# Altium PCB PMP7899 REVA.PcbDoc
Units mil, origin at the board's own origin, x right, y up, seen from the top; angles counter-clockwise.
Board outline 4000 x 1400 mil, 4 copper layers (Top Layer, MidLayer1, MidLayer2, Bottom Layer), stack 62.6 mil thick; 69 components, 27 nets, 146 pads, 45 vias.
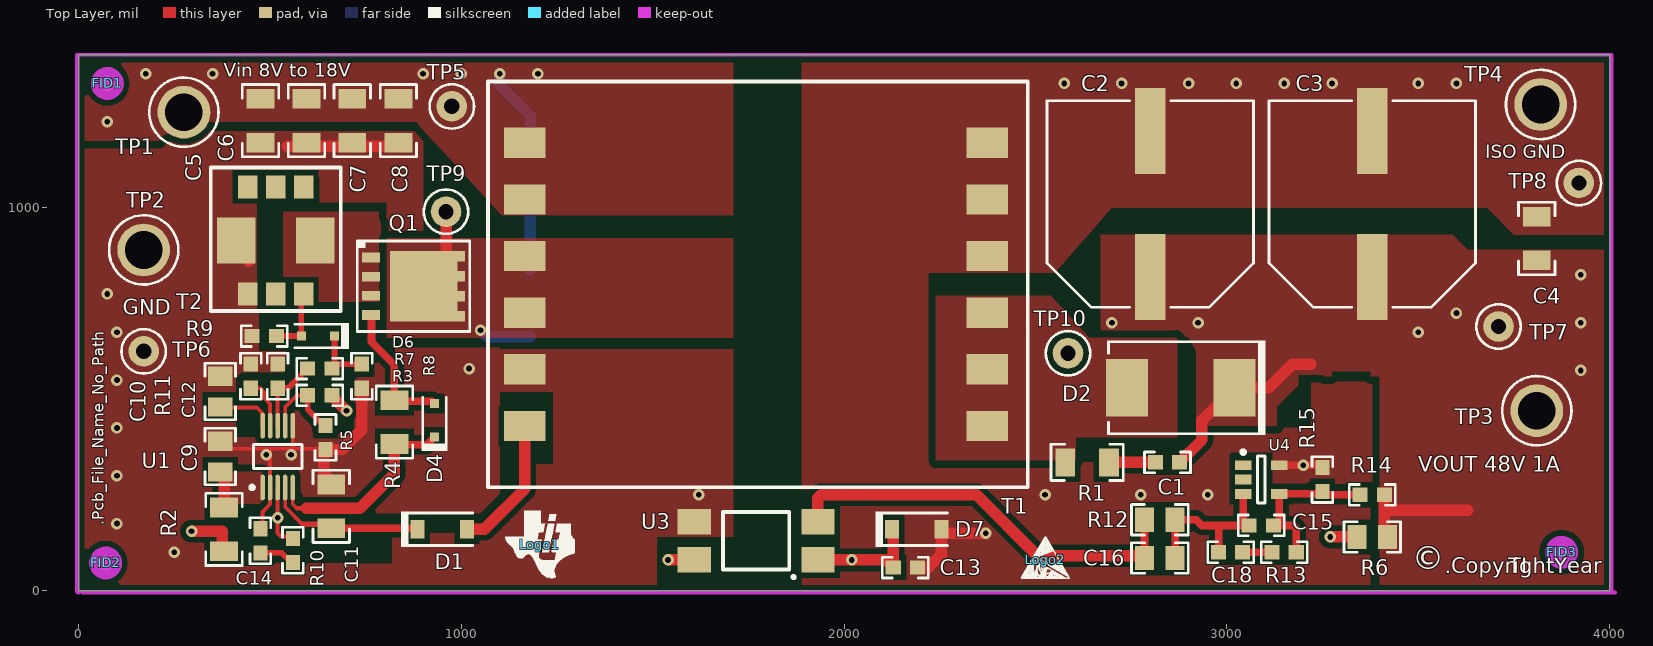
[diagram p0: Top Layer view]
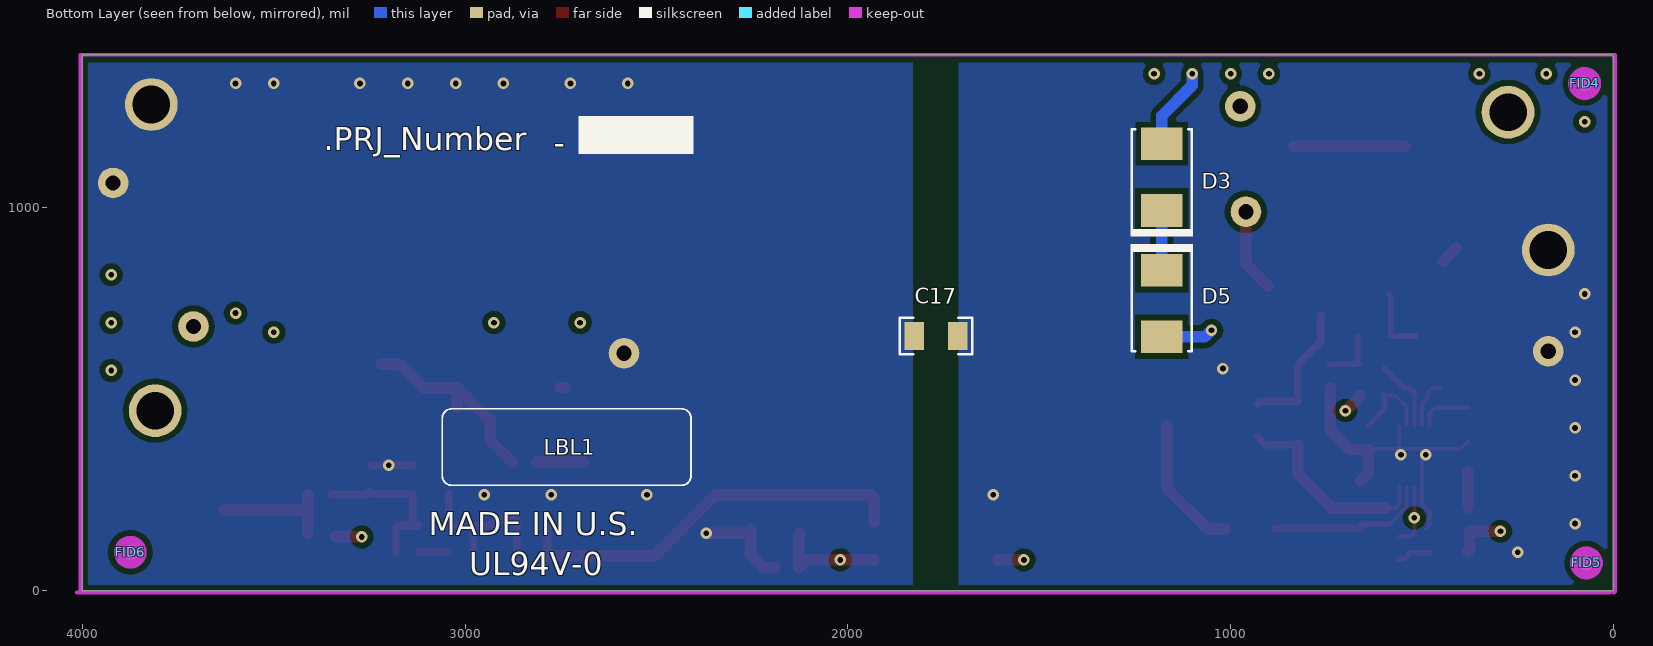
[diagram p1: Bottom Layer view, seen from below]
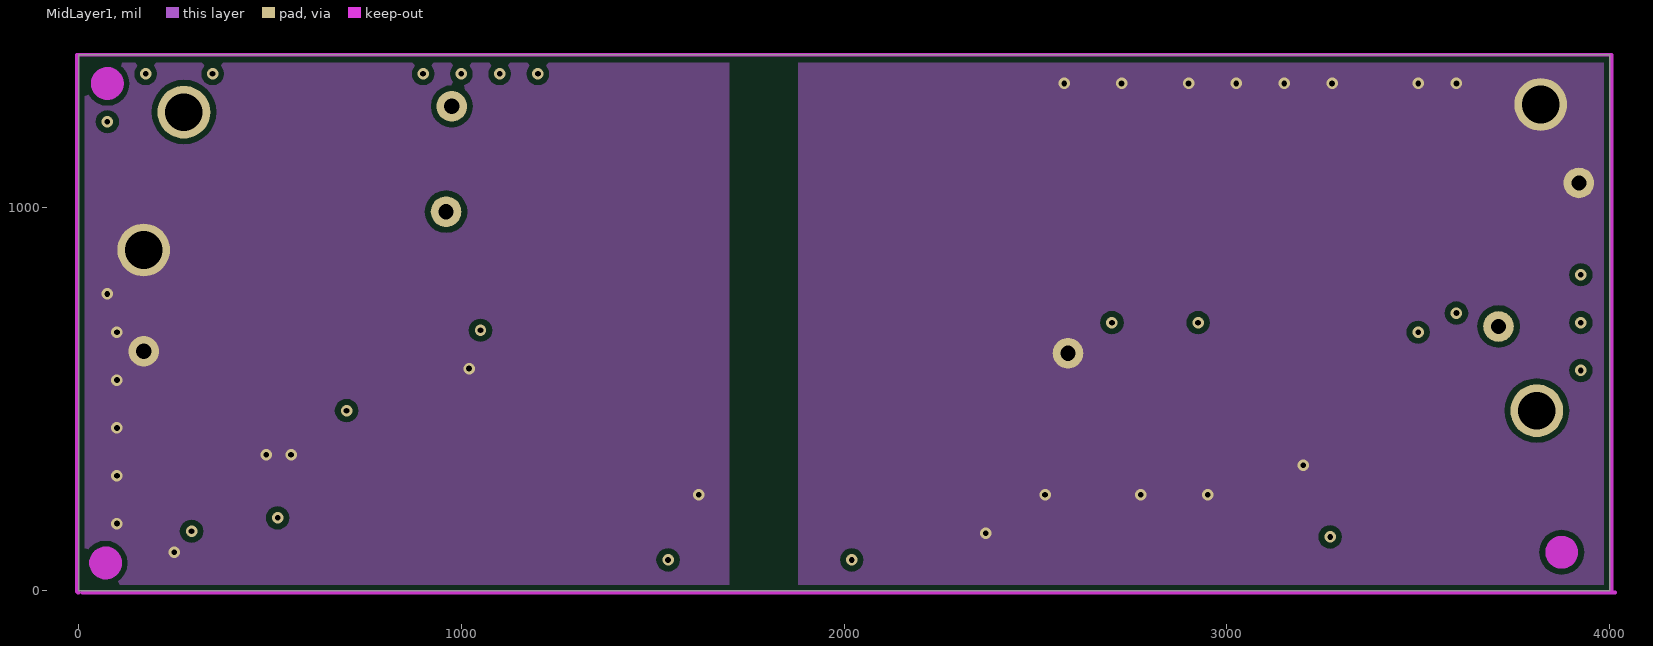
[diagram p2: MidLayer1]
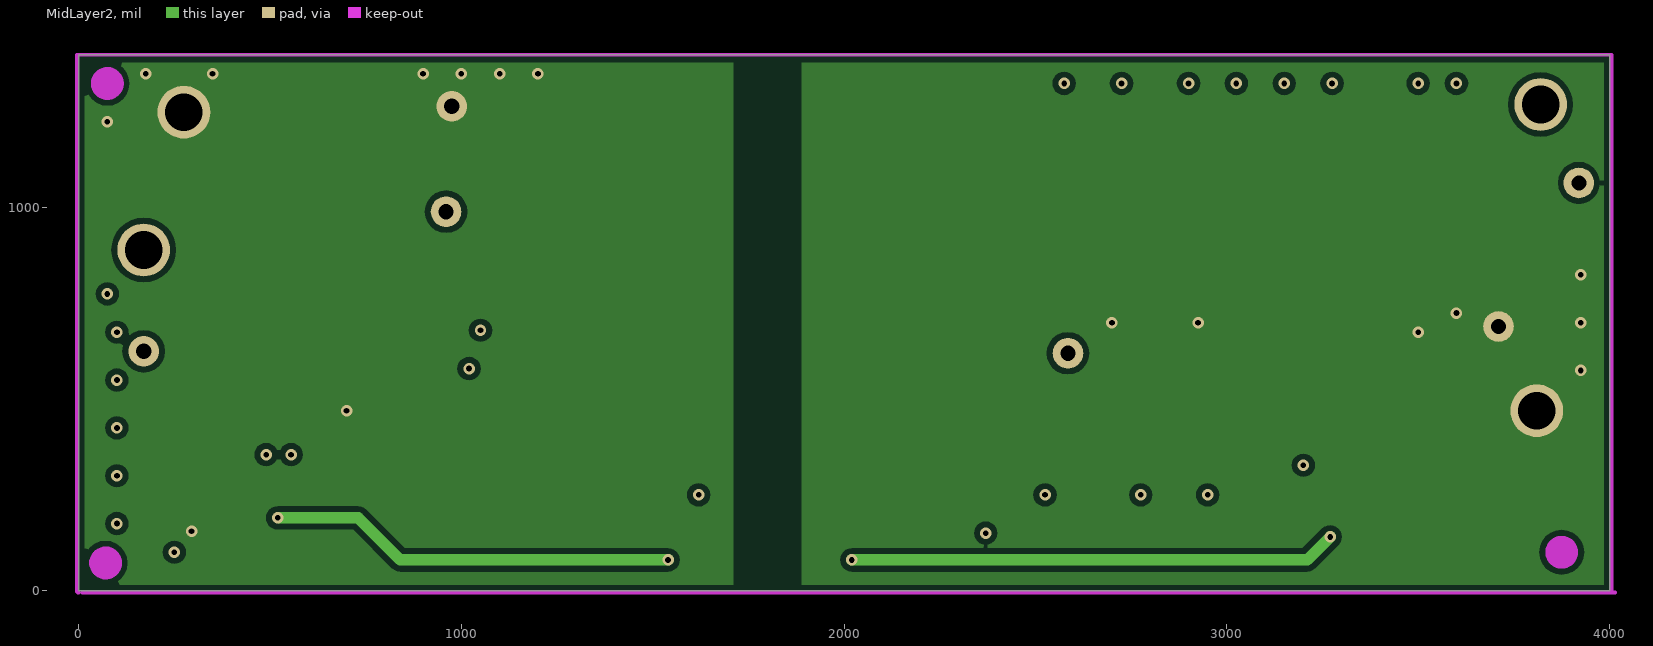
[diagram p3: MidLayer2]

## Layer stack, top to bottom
Top Layer: signal copper 1.4
Dielectric: prepreg 19, FR-4, Dk 4.8
MidLayer1: signal copper 1.4
Dielectric: core 19, FR-4, Dk 4.8
MidLayer2: signal copper 1.4
Dielectric: prepreg 19, FR-4, Dk 4.8
Bottom Layer: signal copper 1.4

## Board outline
0,0 0,1400 4000,1400 4000,0

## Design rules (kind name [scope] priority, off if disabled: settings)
AcuteAngle [All] p1: minimum=4.50000000000000E+0001 checktracksonly=FALSE
AssemblyTestPointUsage [All] p1: valid=2
Clearance "Clearance_Polygon to Polygon" [IsRegion vs IsRegion] p1: gap=20
Clearance Clearance_Polygon [IsRegion] p2: gap=15
Clearance Clearance_BoardEdge_MountingHoles [OnCopper and InComponentClass('Mounting Holes') vs IsKeepOut] p3: gap=40
Clearance Clearance_BoardEdge_Poly [OnCopper and InPoly vs IsKeepOut] p4: gap=25
Clearance Clearance_BoardEdge [OnCopper and Not InComponentClass('Logo') and not InComponentClass('FiducialMark') and not InRegion(1000,500,4000,800) vs IsKeepOut] p5: gap=75
Clearance [All] p6: gap=10
ComponentClearance ComponentClearance_Logo [InComponentClass(Logo)] p1: gap=50 collisioncheckmode=3 verticalgap=10 showdistances=FALSE
ComponentClearance ComponentClearance_ScrewToNut [(HasFootprint('NY PMS 440 0025 PH')) vs (HasFootprint('Keystone_1902C'))] p2: gap=5 collisioncheckmode=3 verticalgap=10 showdistances=FALSE
ComponentClearance ComponentClearance_MountingHoles [InComponentClass('Mounting Holes')] p3: gap=250 collisioncheckmode=3 verticalgap=100000 showdistances=FALSE
ComponentClearance ComponentClearance_SmallPassives [HasFootprint('0201*') or HasFootprint('0402*') or HasFootprint('0508') or HasFootprint('0603*') or HasFootprint('0612') or HasFootprint('0805*') or HasFootprint('0815*') or HasFootprint('0830*') or HasFootprint('1206*') or HasFootprint('1210*') or HasFootprint('1808*') or HasFootprint('1812*') or HasFootprint('1825*') or HasFootprint('2010*') or HasFootprint('2220*') or HasFootprint('2225*') or HasFootprint('2512*') or HasFootprint('2728*') or HasFootprint('3518*') vs HasFootprint('0201*') or HasFootprint('0402*') or HasFootprint('0508') or HasFootprint('0603*') or HasFootprint('0612') or HasFootprint('0805*') or HasFootprint('0815*') or HasFootprint('0830*') or HasFootprint('1206*') or HasFootprint('1210*') or HasFootprint('1808*') or HasFootprint('1812*') or HasFootprint('1825*') or HasFootprint('2010*') or HasFootprint('2220*') or HasFootprint('2225*') or HasFootprint('2512*') or HasFootprint('2728*') or HasFootprint('3518*')] p4: gap=20 collisioncheckmode=3 verticalgap=10 showdistances=FALSE
ComponentClearance ComponentClearance_THtoSMT [IsThruComponent vs IsSMTComponent] p5: gap=100 collisioncheckmode=3 verticalgap=100000 showdistances=FALSE
ComponentClearance ComponentClearance_THtoTH [IsThruComponent vs IsThruComponent] p6: gap=118.11 collisioncheckmode=3 verticalgap=100000 showdistances=FALSE
ComponentClearance [All] p7: gap=40 collisioncheckmode=3 verticalgap=10 showdistances=FALSE
DiffPairsRouting [All] p1: maxlimit=100 minlimit=10 mostfreqgap=10 maxuncoupledlength=1000
FabricationTestPointUsage TestPointUsage [All] p1: valid=2 allowmultiple=FALSE
FabricationTestpoint Testpoint [All] p1: side=3 testpointundercomponent=TRUE minsize=40 maxsize=100 preferedsize=60 minholesize=0 maxholesize=40 preferedholesize=32 testpointgrid=1 allowsidetop=TRUE allowsidebottom=TRUE usegrid=TRUE gridtolerance=0.01
FanoutControl Fanout_LCC [IsLCC] p1: bgadir=Out bgaviamode=Centered fanoutstyle=Auto fanoutdirection=Alternating viagrid=1 // Fanout_LCC (Default Rule)
FanoutControl Fanout_BGA [IsBGA] p2: bgadir=Out bgaviamode=Centered fanoutstyle=Auto fanoutdirection=Alternating viagrid=1 // Fanout_BGA (Default Rule)
FanoutControl Fanout_Default [All] p4: bgadir=Out bgaviamode=Centered fanoutstyle=Auto fanoutdirection=Alternating viagrid=1 // Fanout_Default (Default Rule)
FanoutControl Fanout_Small [(CompPinCount < 5)] p5: bgadir=Out bgaviamode=Centered fanoutstyle=Auto fanoutdirection=OutThenIn viagrid=1 // Fanout_Small (Default Rule)
HoleSize [All] p1: absolutevalues=TRUE maxlimit=251 minlimit=8 maxpercent=80.000 minpercent=20.000
MinimumAnnularRing [All] p1: minimumring=6
MinimumSolderMaskSliver MinimumSolderMaskSliver_Logo [InComponentClass('Logo') vs InComponentClass('Logo')] p1: minsoldermaskwidth=0.7
MinimumSolderMaskSliver [All] p2: minsoldermaskwidth=4
PlaneConnect [All] p1: planeconnectstyle=Relief reliefexpansion=10 reliefentries=4 reliefconductorwidth=10 reliefairgap=10
PolygonConnect [All] p1: connectstyle=Direct reliefconductorwidth=10 reliefentries=4 polygonreliefangle="90 Angle" airgapwidth=10
RoomDefinition "PMP7899 schematic Rev3" [InComponentClass('PMP7899 schematic Rev3')] p1 off: confinementstyle=ConfineIn formatcopy=TRUE lockcomponents=FALSE outline -692,-1534 1308,-1534 1308,-534 -692,-534
RoutingVias [All] p1: holewidth=16 width=34 viastyle="Through Hole" minholewidth=8 minwidth=26 maxholewidth=40 maxwidth=65
SMDToCorner [All] p1: distance=30000
SilkToSilkClearance [All] p1: silktosilkclearance=5
SilkscreenOverComponentPads [All] p1: minsilkscreentomaskgap=5
SolderMaskExpansion [All] p1: expansion=3
Width [All] p1: maxlimit=100 minlimit=10 preferedwidth=10 checkconnectedcopper=TRUE
14 further rules are at their usual default settings.

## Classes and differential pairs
component class "PMP7899 schematic Rev3": C1 C2 C3 C4 C5 C6 C7 C8 C9 C10 C11 C12 C13 C14 C15 C16 C17 C18 D1 D2 D3 D4 D5 D6 D7 Q1 R1 R2 R3 R4 R5 R6 R7 R8 R9 R10 R11 R12 R13 R14 R15 T1 T2 TP1 TP2 TP3 TP4 TP5 TP6 TP7 TP8 TP9 TP10 U1 U3 U4
component class Logo: Logo1
component class Hardware_ANSI-B: FID1 FID2 FID3 FID4 FID5 FID6 LBL1 Logo1 Logo2 ZZ1 ZZ2 ZZ3 ZZ4
component class FiducialMark: FID1 FID2 FID3 FID4 FID5 FID6
component class AssemblyNote: ZZ1 ZZ2 ZZ3 ZZ4
component class Label: LBL1

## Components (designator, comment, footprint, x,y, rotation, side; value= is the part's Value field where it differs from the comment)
C1 "C1608C0G2A101J" 0603 2845,335 r180 top
C2 "Panasonic, EEV-FK1J151Q" SM_RADIAL_H13 2800,1010 r90 top
C3 "EEV-FK1J151Q" SM_RADIAL_H13 3380,1010 r90 top
C4 "GRM31MR71H105KA88L" 1206 3810,920 r90 top
C5 "GRM31CR71E106KA12L" 1206 475,1227.52 r270 top
C6 "GRM31CR71E106KA12L" 1206 595,1227.52 r270 top
C7 "GRM31CR71E106KA12L" 1206 715,1227.52 r270 top
C8 "GRM31CR71E106KA12L" 1206 835.32,1227.52 r270 top
C9 "C2012X5R1E105K" 0805_HV 370,350 r90 top
C10 "C2012C0G1E103J" 0805_HV 370,520 r90 top
C11 "GRM31CR61E106KA12L" 1206 660,220 r90 top
C12 "C1608C0G1H101J" 0603 520,560 r90 top
C13 "GRM188R61C105KA93D" 0603 2160,60 r0 top
C14 "C0603C104K3RACTU" 0603 475,130 r90 top
C15 "C1608C0G2A101J" 0603 3090,170 r0 top
C16 "C2012Y5V1H105Z" 0805_HV 2825,85 r180 top
C17 "C1206C102KFRACTU" 1206 1770,665 r180 bottom
C18 "C0603C104J3RACTU" 0603 3010,100 r180 top
D1 "1N4148W-7-F" SOD-123 950,160 r0 top
D2 "ES3J" SMC 2880,530 r180 top
D3 "DNP, On Semi, 1SMB5939BT3G" SMB 1180,1080 r90 bottom
D4 "BAT54HT1G" sod-323 930,445 r90 top
D5 "DNP, Diodes Inc, MBRS1100T3G" SMB 1180,750 r270 bottom
D6 "BAT54HT1G" sod-323 625,665 r180 top
D7 "Vishay, MMSZ4699-V" SOD-123 2190,160 r0 top
FID1 "Fiducial" Fiducial10-20 75,1325 r0 top
FID2 "Fiducial" Fiducial10-20 70.46,72.11 r0 top
FID3 "Fiducial" Fiducial10-20 3875,100 r0 top
FID4 "Fiducial" Fiducial10-20 75,1325 r180 bottom
FID5 "Fiducial" Fiducial10-20 70.46,72.11 r180 bottom
FID6 "Fiducial" Fiducial10-20 3875,100 r180 bottom
LBL1 "Size: 0.65\" x 0.20 \"" Label_650x200 2735,375 r180 bottom
Logo1 "Texas Instruments" TI_Symbol_Overlay_Small 1205,120 r0 top
Logo2 "ESD Susceptible" ESD_Overlay_Small 2525,80 r0 top
Q1 "Infineon, BSC067N06LS3 G" PG-TDSON-8 875,795 r0 top
R1 "CRCW1206100RFKEA" 1206 2635,335 r180 top
R2 "CRCW12063R32FKEA" 1206 380,160 r270 top
R3 "CRCW060346K4FKEA" 0603 630,510 r0 top
R4 "CRCW12060000Z0EA" 1206 825,440 r270 top
R5 "CRCW060310K0FKEA" 0603 645,400 r90 top
R6 "CRCW080510K0FKEA" 0805_HV 3380,140 r0 top
R7 "CRCW06031K00FKEA" 0603 630,580 r0 top
R8 "CRCW06033R01FKEA" 0603 740,560 r90 top
R9 "CRCW060310K0FKEA" 0603 485,665 r0 top
R10 "CRCW06031K00FKEA" 0603 560,105 r270 top
R11 "CRCW060349K9FKEA" 0603 450,560 r270 top
R12 "CRCW0805499RFKEA" 0805_HV 2825,185 r0 top
R13 "CRCW06033K16FKEA" 0603 3150,100 r180 top
R14 "CRCW060337K4FKEA" 0603 3380,250 r0 top
R15 "CRCW06031K00FKEA" 0603 3250,290 r90 top
T1 "NA6264-AL" NA62XX-AL 1770,800 r0 top
T2 "PA1005.100NLT" PA1005.XXXNL 515,915 r0 top
TP1 "Vin 8V to 18V" Keystone1502-2 275,1250 r0 top
TP2 "GND" Keystone1502-2 170,890 r0 top
TP3 "VOUT 48V 1A" Keystone1502-2 3810,470 r0 top
TP4 "ISO GND" Keystone1502-2 3820,1270 r0 top
TP5 "5000" Keystone5000 975,1265 r0 top
TP6 "5001" Keystone5001 170,625 r0 top
TP7 "5000" Keystone5000 3710,690 r0 top
TP8 "5001" Keystone5001 3920,1065 r0 top
TP9 "5002" Keystone5002 960,990 r0 top
TP10 "5002" Keystone5002 2585,620 r0 top
U1 "TI, LM5022" MUB10A_N 520,350 r90 top
U3 "PS2501L-1-A" PS2501L 1770,130 r180 top
U4 "TI, LMV431ACM5" MF05A_N 3090,290 r0 top
ZZ1 "This Assembly Note is for PCB labels only" AssemblyNoteLabel 185,3938 r0 top
ZZ2 "These assemblies are ESD sensitive, ESD precautions shall be observed." AssemblyNote 185,3829.11 r0 top
ZZ3 "These assemblies must be clean and free from flux and all contaminants. Use of no clean flux is not acceptable." AssemblyNote 185,3740.56 r0 top
ZZ4 "These assemblies must comply with workmanship standards IPC-A-610 Class 2., unless otherwise specified." AssemblyNote 185,3652 r0 top

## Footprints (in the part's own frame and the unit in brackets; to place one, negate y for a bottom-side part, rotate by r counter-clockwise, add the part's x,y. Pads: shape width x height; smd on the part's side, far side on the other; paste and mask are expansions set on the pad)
0603 [mm] "0603 from SM-752 data"
  rect 1x0.95 smd: 1(-0.8,0) 2(0.8,0)
  silkscreen extent -1.52,-0.69 1.52,0.69, body extent -0.87,-0.47 0.87,0.47, height 0.85
0805_HV [mil] "0805 with 30mil clearance between pads"
  rect 50x63 smd: 1(-40,0) 2(40,0)
  silkscreen extent -74,-40 74,40, body extent -43,-29 43,29, height 43
1206 [mm] "1206 from SM-752 data"
  rect 1.3x1.85 smd: 1(-1.45,0) 2(1.45,0)
  silkscreen extent -2.4,-1.21 2.4,1.21, body extent -1.7,-0.9 1.7,0.9, height 1.35
AssemblyNote [mil] "Assembly Note"
AssemblyNoteLabel [mil] "Assembly Note for PCB Labels"
ESD_Overlay_Small [mil]
  silkscreen extent -62,-48 64,61
Fiducial10-20 [mm]
  round 1 smd paste-0.5 mask+0.5: 1(0,0)
  Keep-Out Layer circle w1.178: c0,0 r0.5
Keystone1502-2 [mm] "Double Turret"
  round 3.5 hole 2.5: 1(0,0)
  silkscreen extent -2.3,-2.3 2.3,2.3, body extent -1.61,-1.61 1.61,1.61, height 5.56
Keystone5000 [mil] "For Keystone 500x miniature loop terminals"
  round 80 hole 40: 1(0,0)
  silkscreen extent -58,-58 58,58, body extent -49,-49 49,49, height 182
Keystone5001 [mil] "For Keystone 500x miniature loop terminals"
  round 80 hole 40: 1(0,0)
  silkscreen extent -58,-58 58,58, body extent -49,-49 49,49, height 182
Keystone5002 [mil] "For Keystone 500x miniature loop terminals"
  round 80 hole 40: 1(0,0)
  silkscreen extent -58,-58 58,58, body extent -49,-49 49,49, height 182
Label_650x200 [mil] "Thermal Transfer Label"
  silkscreen extent -325,-100 325,100, body extent -326,-101 326,101, height 1
MF05A_N [mm] "SOT23, 5-Leads, Body 2.9x1.6mm, Pitch 0.95mm, Lead Span 2.8mm, IPC Medium Density"
  rect 1.1x0.65 smd: 1(-1.2,0.95) 2(-1.2,0) 3(-1.2,-0.95) 4(1.2,-0.95) 5(1.2,0.95)
  silkscreen extent -1.32,-1.55 0.25,1.95, body extent -0.9,-1.55 0.9,1.55, height 1.19
MUB10A_N [mm] "TSSOP, 10-Leads, Body 3x3mm, Pitch 0.5mm, IPC Medium Density"
  oval 1.7x0.3 smd: 1(-2.05,1) 2(-2.05,0.5) 3(-2.05,0) 4(-2.05,-0.5) 5(-2.05,-1) 6(2.05,-1) 7(2.05,-0.5) 8(2.05,0) 9(2.05,0.5) 10(2.05,1)
  silkscreen extent -2.17,-1.6 0.8,1.82, body extent -1.6,-1.6 1.6,1.6, height 1.09
NA62XX-AL [mil] "COILCRAFT TRANFORMER"
  round 60 on Top Overlay: 0(-750,370)
  rect 108x79 smd: 1(-604,370) 2(-604,222) 3(-604,74) 4(-604,-74) 5(-604,-222) 6(-604,-370) 7(604,-370) 8(604,-222) 9(604,-74) 10(604,74) 11(604,222) 12(604,370)
  silkscreen extent -700,-530 710,530, body extent -700,-530 710,530, height 560
PA1005.XXXNL [mil] "PULSE ENGINEERING PA1005.XXXNL SERIES"
  round 30 on Top Overlay: 0(-145,-225)
  rect 50x60 smd: 1(-73,-140) 2(0,-140) 3(73,-140) 4(73,140) 5(0,140) 6(-73,140)
  rect 100x120 smd: 7(103,0) 8(-103,0)
  silkscreen extent -170,-185 170,190, body extent -170,-185 170,190, height 190
PG-TDSON-8 [mm] "Infineon recommended land pattern"
  rect 1.2x0.65 smd: 1(-2.825,1.905) 2(-2.825,0.635) 3(-2.825,-0.635) 4(-2.825,-1.905)
  rect 0.5x0.7 smd: 5(3.175,-2) 6(3.175,-0.675) 7(3.175,0.675) 8(3.175,2)
  rect 4.5x4.7 smd paste-2.25: 9(0.675,0)
  silkscreen extent -3.74,-3 3.74,3, body extent -3.17,-2.89 3.17,2.9, height 1.1
PS2501L [mm] "NEC optocoupler"
  rect 2.2x1.7 smd: 1(-4.1,1.27) 2(-4.1,-1.27) 3(4.1,-1.27) 4(4.1,1.27)
  silkscreen extent -2.57,-1.9 2.2,2.49, body extent -3.5,-2.47 3.5,2.47, height 3.8
SM_RADIAL_H13 [mm] "12.5 x 13.5mm:  Panasonic H13"
  rect 5.7x2 smd: 1(-4.85,0) 2(4.85,0)
  silkscreen extent -6.85,-6.85 6.85,6.85, body extent -6.85,-6.85 6.85,6.85, height 14
SMB [mil] "Molded Diode, 2-Leads, Body 5.4x3.6mm, IPC Medium Density, based on OnSemi component dimensions"
  rect 85x107.99 smd: 1(-87.01,0) 2(87.01,0)
  silkscreen extent -155,-82 125,82, body extent -106,-71 106,71, height 91
SMC [mil] "Molded Diode, 2-Leads, Body 6.9x5.8mm, IPC Medium Density, based on OnSemi component dimensions and land patterns"
  rect 110x150 smd: 1(-140.49,0) 2(140.49,0)
  silkscreen extent -221,-124 189,123, body extent -156,-116 156,116, height 91
SOD-123 [mm] "On Semi recommended land pattern"
  rect 0.915x1.22 smd: 1(-1.637,0) 2(1.637,0)
  silkscreen extent -2.74,-1.17 2.03,1.17, body extent -1.93,-0.9 1.93,0.9, height 1.35
sod-323 [mm] "NXP recommended land pattern"
  rect 0.6x0.6 smd paste-0.05: 1(-1.1,0) 2(1.1,0)
  silkscreen extent -2.06,-0.86 1.53,0.86, body extent -1.3,-0.67 1.3,0.68, height 1.1
TI_Symbol_Overlay_Small [mil]
  silkscreen extent -90,-88 91,88

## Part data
C1 C15: "CAP, CERM, 100pF, 100V, +/-5%, C0G/NP0, 0603"
C2: library part EEV-FK1J151Q, "CAP, AL, 150uF, 63V, +/-20%, 0.16 ohm, SMD"
C3: "CAP, AL, 150uF, 63V, +/-20%, 0.16 ohm, SMD"
C4: "CAP, CERM, 1uF, 50V, +/-10%, X7R, 1206"
C5 C6 C7 C8: "CAP, CERM, 10uF, 25V, +/-10%, X7R, 1206"
C9: "CAP, CERM, 1uF, 25V, +/-10%, X5R, 0805"
C10: "CAP, CERM, 0.01uF, 25V, +/-5%, C0G/NP0, 0805"
C11: "CAP, CERM, 10uF, 25V, +/-10%, X5R, 1206"
C12: "CAP, CERM, 100pF, 50V, +/-5%, C0G/NP0, 0603"
C13: "CAP, CERM, 1uF, 16V, +/-10%, X5R, 0603"
C14: "CAP, CERM, 0.1uF, 25V, +/-10%, X7R, 0603"
C16: "Capacitor"
C17: "CAP CER 1000PF 1.5KV X7R 1206"
C18: "CAP, CERM, 0.1uF, 25V, +/-5%, X7R, 0603"
D1: "Diode, Ultrafast, 100V, 0.15A, SOD-123"
D2: "DIODE ULTRAFAST 600V 3A DO-214AB"
D3: library part 1SMB5939BT3G, "Diode, Zener, 39V, 550mW, SMB"
D4 D6: "Diode, Schottky, 30V, 0.2A, SOD-323"
D5: library part MBRS1100T3G, "Diode, Schottky, 100V, 1A, SMB"
D7: library part MMSZ4699-V, "Diode, Zener, 12V, 500mW, SOD-123"
FID1 FID2 FID3 FID4 FID5 FID6: "Fiducial mark.  There is nothing to buy or mount."
LBL1: library part THT-14-423-10, "Thermal Transfer Printable Labels, 0.650\" W x 0.200\" H - 10,000 per roll"
Logo1: library part TI_Logo, "Texas Instrument Corporate Signature"
Logo2: library part ESD_Susceptible, "ESD Susceptible Symbol"
Q1: library part "BSC067N06LS3 G", "MOSFET, N-CH, 60V, 50A, PG-TDSON-8"
R1: "RES, 100 ohm, 1%, 0.25W, 1206"
R2: "RES, 3.32 ohm, 1%, 0.25W, 1206"
R3: "RES, 46.4k ohm, 1%, 0.1W, 0603"
R4: "RES, 0 ohm, 5%, 0.25W, 1206"
R5 R9: "RES, 10.0k ohm, 1%, 0.1W, 0603"
R6: "RES, 10.0k ohm, 1%, 0.125W, 0805"
R7 R10 R15: "RES, 1.00k ohm, 1%, 0.1W, 0603"
R8: "RES, 3.01 ohm, 1%, 0.1W, 0603"
R11: "RES, 49.9k ohm, 1%, 0.1W, 0603"
R12: "RES, 499 ohm, 1%, 0.125W, 0805"
R13: "RES, 3.16k ohm, 1%, 0.1W, 0603"
R14: "RES, 37.4k ohm, 1%, 0.1W, 0603"
T1: "COILCRAFT TRANSFORMER"
T2: "XFRMR CURR SENSE 2.0MH 1:100 SMD"
TP1 TP2 TP3 TP4: library part 1502-2, "Terminal, Turret, TH, Double"
TP5 TP7: "Test Point, TH, Miniature, Red"
TP6 TP8: "Test Point, TH, Miniature, Black"
TP9 TP10: "Test Point, TH, Miniature, White"
U1: library part LM5022MME/NOPB, "60V Low Side Controller for Boost and SEPIC, 10-pin MSOP, Pb-Free"
U3: "High Isolation Voltage Single Transistor Type OptoCoupler"
U4: library part LMV431ACM5, "Low-Voltage (1.24V) Adjustable Precision Shunt Regulator, 5-pin SOT-23"
ZZ1: library part AssemblyNoteLabel
ZZ2 ZZ3 ZZ4: library part AssemblyNote

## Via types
v1: diameter 30, hole 15, Top Layer to Bottom Layer, 45 vias

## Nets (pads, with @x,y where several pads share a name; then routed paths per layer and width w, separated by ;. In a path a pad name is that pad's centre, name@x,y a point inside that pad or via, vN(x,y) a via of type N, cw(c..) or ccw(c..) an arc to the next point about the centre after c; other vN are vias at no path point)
COMP: R10.1 U1.3 U3.4 | length 1292
  Top Layer w10: U1.3 v1(520,190) 520,150 528.5,141.5 R10.1@560,141.5
  Top Layer w30: v1(1540,80) U3.4
  MidLayer2 w30: v1@525,190 730,190 840,80 v1(1540,80)
CS: C12.1 R7.1 U1.8 | length 188.3
  Top Layer w10: U1.8 C12.1@520,521.46
  Top Layer w15: C12.1@527.05,521.46 535.59,530 547.2,530 547.2,528.7 R7.1
GND: C5.2 C6.2 C7.2 C8.2 C9.2 C10.2 C11.2 C12.2 C14.2 C17.2 R5.1 R8.1 R9.1 R11.1 T1.5 T2.1 T2.8 TP2.1 TP6.1 U1.2 U1.6 U3.3 | length 1209.8
  Top Layer w10: C9.2@380,390 399.37,370.63 500,370.63 ; C14.2@490,161.5 480,171.5 480,205 500.31,225.31 U1.2 500.31,370.31 500,370.63 ; U1.6 559.37,370.63 ; R5.1@640,368.5 637.87,370.63 559.37,370.63 ; 500,370.63 559.37,370.63
  Top Layer w30: T2.8@410,895 T2.8@445,860 ; 545.32,1160.43 C8.2@835.32,1160.43 ; C11.2@660,287.09 640,307.09 640,368.5 688.5,368.5 740,420 R8.1
  other v1: 250,100 100,175 1620,250 100,300 490,355 555,355 100,425 100,550 1020,580 100,675 75,775
"ISO GND": C2.2 C3.2 C4.2 C13.2 C17.1 D7.2 R15.2 T1.10 T1.11 T1.12 TP4.1 TP8.1 TP10.1 U4.5 | length 354
  Top Layer w20: U4.5 R15.2@3244.09,327.4
  Top Layer w30: C13.2 2220,60 2255,95 2254.47,95.53 D7.2 ; D7.2@2266.05,150 2340,150 v1(2370,150)
  other v1: 2525,250 2775,250 2950,250 3200,327.4 2575,1325 2725,1325 2900,1325 3025,1325 3150,1325 3275,1325 3500,1325 3600,1325
NetC1_2: C1.2 R1.1 | length 121.4
  Top Layer w30: R1.1 C1.2
NetC13_1: C13.1 D7.1 R6.1 U3.1 | length 1641.5
  Top Layer w30: U3.1 v1(2020,80) 2108.5,80 C13.1 2128.5,147.03 D7.1@2125.53,150 ; v1(3270,140) R6.1
  MidLayer2 w30: v1(2020,80) 3210,80 v1(3270,140)
NetC14_1: C14.1 R10.2 | length 88.1
  Top Layer w15: C14.1@478.54,98.5 480,98.5 530.04,98.5 546.04,82.5 R10.2@560,82.5
NetC15_1: C15.1 C16.1 C18.2 R12.2 U4.3 | length 458.8
  Top Layer w20: C16.1 R12.2 2920,185 2935,170 2978.5,170 ; C18.2 2978.5,170 ; U4.3 3042.76,185.75 C15.1 2978.5,170
NetC15_2: C15.2 R13.1 R14.1 R15.1 U4.4 | length 426
  Top Layer w20: C15.2 3175,170 3181.5,163.5 R13.1 ; C15.2@3137.24,170 U4.4 3244.09,252.6 R15.1 3258.5,250 R14.1
NetC16_2: C16.2 R12.1 U3.2 | length 1084.8
  Top Layer w20: C16.2 R12.1
  Top Layer w30: U3.2 1931.42,241.42 1940,250 2346,250 2505,91 2784,91 C16.2@2785,90
NetC18_1: C18.1 R13.2 | length 77
  Top Layer w20: C18.1@3044.94,100 R13.2@3121.95,100
NetD1_2: D1.2 T1.6 | length 359.4
  Top Layer w30: D1.2 1060,160 1166,266 T1.6
NetD2_2: D2.2 R1.2 T1.7 T1.8 T1.9 | length 10.5
  Top Layer w30: D2.2 D2.2@2750,530
NetD3_1: D3.1 D5.1 | length 156
  Bottom Layer w30: D5.1 D3.1
NetD4_2: D4.2 Q1.4 R4.1 | length 358.1
  Top Layer w20: Q1.4 765,718.78 765,650 825,590 825,495 923.31,495 D4.2
NetD5_2: D5.2 Q1.5 Q1.6 Q1.7 Q1.8 Q1.9 T1.3 T1.4 TP9.1 | length 356.2
  Top Layer w30: Q1.9 960,853.43 TP9.1
  Bottom Layer w30: v1(1050,680) 1067.01,662.99 D5.2
NetD6_1: D6.1 R7.2 R8.2 | length 154.8
  Top Layer w15: D6.1 668.31,596.81 662.99,591.5 R8.2 R8.2@741.5,590
NetD6_2: D6.2 R9.2 T2.3 | length 177.8
  Top Layer w15: R9.2 D6.2 581.69,768.69 T2.3
NetQ1_1: Q1.1 Q1.2 Q1.3 T2.7
OUT: D4.1 R4.2 U1.5 | length 540.5
  Top Layer w10: U1.5 559.37,225.63 570,215
  Top Layer w12: 570,215 595,215
  Top Layer w20: R4.2@825,380.94 909.25,380.94 D4.1
  Top Layer w30: 595,215 735,215 825,305 R4.2@825,380.94
RT: R11.2 U1.9 | length 133.1
  Top Layer w10: R11.2 474.76,528.5 485,518.27 485,503.5 500.31,488.19 U1.9
SS: C10.1 U1.10 | length 139.6
  Top Layer w10: C10.1@380,478.5 465.51,478.5 480.63,463.39 U1.10
UVLO: R3.1 R5.2 U1.7 | length 216
  Top Layer w10: U1.7 539.68,479.68 570,510 R3.1
  Top Layer w15: R3.1 598.5,472.99 R5.2@640,431.5
VCC: C11.1 D1.1 U1.4 | length 412.6
  Top Layer w10: U1.4 539.68,218.58 585.35,172.91
  Top Layer w15: 585.35,172.91 C11.1@660,172.91
  Top Layer w20: C11.1 D1.1@882.62,162.91
VIN: C5.1 C6.1 C7.1 C8.1 D3.2 R2.2 R3.2 T1.1 T1.2 TP1.1 TP5.1 | length 404.7
  Top Layer w30: v1(295,155) 375,155 375,107.91 R2.2 ; R3.2@661.5,508.5 v1(700,470)
  Bottom Layer w30: v1(1100,1350) 1100,1320 1180,1240 D3.2
  other v1: 75,1225 175,1350 350,1350 900,1350 1000,1350 1200,1350
"VIN U1": C9.1 R2.1 U1.1 | length 92.9
  Top Layer w30: R2.1 C9.1@380,310
VOUT: C1.1 C2.1 C3.1 C4.1 D2.1 R6.2 R14.2 TP3.1 TP7.1 | length 850.6
  Top Layer w30: C1.1 2935,393.5 2935,444.51 D2.1 ; D2.1@3020.49,479 D2.1 ; 3220,591.5 3171.5,591.5 3110,530 D2.1 ; R6.2@3411.5,148.5 3411.5,210 ; R14.2 3411.5,210 ; 3630,210 3411.5,210
  other v1: 3925,575 3500,675 2700,700 2925,700 3925,700 3600,725 3925,825
pads on no net: FID1.1 FID2.1 FID3.1 FID4.1 FID5.1 FID6.1 T1.0 T2.0 T2.2 T2.4 T2.5 T2.6 U4.1 U4.2

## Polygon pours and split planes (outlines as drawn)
"ISO GND" on Top Layer "Top Layer-ISO GND" (solid, pour order 20): 1890,0 1890,265 3376.32,265 3375,263.68 3375,0
"ISO GND" on Top Layer "Top Layer-ISO GND" (solid, remove dead copper, pour order 26): 4000,1400 1890,1400 1890,265 2355,265 2490,125 3010,128.54 3011.26,360.87 3120,360 3120,280 3395,278.54 3395,545 3220,545 3220,425 2955,425 2876.5,335 2220,335 2220,830 2550.65,830 2700,1000 3680,1000 3750,930 4000,930
NetD2_2 on Top Layer "Top Layer-D2_2" (solid, remove dead copper, pour order 28): 2240,770 2540,770 2640,660 2849.92,659.92 2850,660 2870,659.92 2870,400.08 2605,399.99 2605,340 2240,340
GND on Top Layer "Top Layer-GND" (solid, pour order 27): 390,400 560,400 560,470 604.55,470 610,410 720,410 721.3,550 720,550 720,635 1100,635 1100,202.5 575,202.5 575,320 390,319.41
"VIN U1" on Top Layer "Top Layer-VIN U1" (solid, remove dead copper, pour order 31): 370,310 370,226.93 473.07,226.93 485,225.98 485,310
VIN on Top Layer "Top Layer-VIN" (solid, pour order 24): 0,1175 210,1175 300,1225 881.57,1225 1105,980 1710,980 1710,1400 0,1400
GND on Top Layer "Top Layer-GND" (solid, remove dead copper, pour order 19): 0,705 410,705 410,74.14 820,70 820,150 1050,150 1050,330 1240,330 1240,520 1050,520 1050,630 1710,630 1710,140 1510,140 1510,0 0,0
GND on Top Layer "Top Layer-GND" (solid, pour order 25): 290,730 470,730 470,625 540,625 540,570 425,570 410,555 410,535 290,535
NetQ1_1 on Top Layer "Top Layer-Q1_1" (solid, remove dead copper, pour order 21): 790,755 790,990 535,990 535,785 615,785 615,755
NetD5_2 on Top Layer " Top Layer-D5_2" (solid, remove dead copper, pour order 22): 1710,920 1710,660 805,660 805,920
VOUT on Top Layer "Top Layer-VOUT" (solid, remove dead copper, pour order 29): 2670,930 3590,930 3630,890 4000,890 4000,0 3400,0 3400,560 3238.85,560 3238.7,550 3200,550 3130,480 3130,430 2920,430 2920,625.71 2900,660 2850,680 2670,680
GND on Top Layer "Top Layer-GND" (solid, remove dead copper, pour order 23): 0,675 465,675 465,1080 630,1080 630,1015 805,1015 805,920 900,920 900,1195 895,1200 220,1200 220,1155 0,1155
VIN on MidLayer2 "MidLayer2-VIN" (solid, remove dead copper, pour order 33): 0,0 0,1400 1710,1400 1710,0
VOUT on MidLayer2 "MidLayer2-VOUT" (solid, remove dead copper, pour order 30): 4005,1400 1890,1400 1890,-5 4000,-5
"ISO GND" on Bottom Layer "Bottom Layer-ISO GND" (solid, remove dead copper, pour order 32): 4005,1400 1830,1400 1830,0 4005,0
GND on Bottom Layer "Bottom Layer-GND" (solid, remove dead copper, pour order 34): 1710,1400 0,1400 0,0 1710,0
GND on MidLayer1 "MidLayer1-GND" (solid, remove dead copper, pour order 36): -5,1400 1700,1400 1700,0 0,0
"ISO GND" on MidLayer1 "MidLayer1-ISO GND" (solid, remove dead copper, pour order 35): 4005,1400 1880,1400 1880,0 3937,0 4000,-63

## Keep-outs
Keep-Out Layer:
  lines w10: 10,-5 4015,-5 ; 4000,1400 -5,1400 -5,0 ; 4005,0 4005,1400 ; -5,0 ccw(c0,0) 0,-5 ; -5,0 ccw(c0,0) 0,-5 ; -5,0 ccw(c0,0) 0,-5 ; -5,0 ccw(c0,0) 0,-5 ; -5,0 ccw(c0,0) 0,-5 ; -5,0 ccw(c0,0) 0,-5
  text ".Layer_Name" at 577,-858.49 h60

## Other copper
Top Layer:
  text ".Layer_Name" at 577,-858.49 h60
Bottom Layer:
  text ".Layer_Name" at 577,-858.49 h60

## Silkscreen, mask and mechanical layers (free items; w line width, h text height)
Top Overlay:
  text ".Pcb_File_Name_No_Path" at 65,170 h30 r90
  text ".CopyrightYear" at 3570,45 h40
  text "TI" at 3735,45 h40
  text "©" at 3485,35 h105
  text ".Layer_Name" at 577,-858.49 h60
Bottom Overlay:
  rectangle: 2404,1140 2704,1240
  text ".PRJ_Number" at 3370,1150 h60
  text "-" at 2769,1139.5 h60
  text "MADE IN U.S." at 3095,145 h60
  text "UL94V-0" at 2990,40 h60
  text ".Layer_Name" at 577,-858.49 h60
Top Paste:
  text ".Layer_Name" at 577,-858.49 h60
Bottom Paste:
  text ".Layer_Name" at 577,-858.49 h60
Top Solder:
  text ".Layer_Name" at 577,-858.49 h60
  text ".Layer_Name" at 577,-858.49 h60
Bottom Solder:
  text ".Layer_Name" at 577,-858.49 h60
Drill Guide:
  text ".Layer_Name" at 577,-858.49 h60
M1 Board Outline:
  the board outline again, w10
  text ".Layer_Name" at 577,-858.49 h60
M2 Board Dimensions:
  rectangle: -0.5,-285.5 124.5,-160.5
  rectangle: 124.5,-410.5 499.5,-285.5
  lines w7: -0.5,-285.5 999.5,-285.5 ; 124.5,-410.5 124.5,-160.5 ; 249.5,-410.5 249.5,-160.5 ; 499.5,-410.5 499.5,-160.5 ; 749.5,-410.5 749.5,-160.5 ; -0.5,-410.5 999.5,-410.5 999.5,-160.5 -0.5,-160.5 -0.5,-410.5
  lines w10: -0.5,-475.5 -0.5,-455.5 ; 59.5,-485.5 -0.5,-465.5 ; 59.5,-445.5 -0.5,-465.5 ; 223.58,-465.5 -0.5,-465.5 ; 775.42,-465.5 999.5,-465.5 ; 939.5,-485.5 999.5,-465.5 ; 939.5,-445.5 999.5,-465.5 ; 999.5,-475.5 999.5,-455.5
  text "1000 (mil)" at 233.58,-501.49 h60
  text ".Layer_Name" at 577,-858.49 h60
M3 3D STEP Top:
  text ".Layer_Name" at 577,-858.49 h60
M4 3D STEP Bottom:
  text ".Layer_Name" at 577,-858.49 h60
M5 Assembly Top:
  lines w7: 5139,110.5 6264,110.5 ; 5139,233 6261.5,233 ; 5454,-9.5 5454,353 ; 5839,-9.5 5139,-9.5 ; 5839,353 5139,353 ; 5139,-9.5 6264,-9.5 6264,353 5139,353 ; 5139,-9.5 5139,353
  lines w10: -292,-930.17 6308,-930.17 ; -292,-726.83 6310,-726.83 ; -292,-523.5 -292,-1133.5 3713,-1133.5 6310,-1133.5 6310,-523.5 -291.5,-523.5 -291.5,-1133.5 1284,-1133.5 ; 2173,-1133.5 2173,-523.5 ; 3440,-726.83 3440,-523.5 ; 4280,-726.83 4280,-523.5 ; 4902,-1140 4902,-937.17
  text "TABLE 1" at 5526.5,388 h40
  text "Variant" at 5164,278 h40
  text "Label text" at 5599,278 h40
  text "001" at 5231.5,158 h40
  text "ChangeMe!" at 5509,155.5 h40
  text "002" at 5231.5,33 h40
  text "ChangeMe!" at 5504,30.5 h40
  text "COMPONENTS MARKED 'DNP' SHOULD NOT BE POPULATED, AND MAY NOT BE IN BILL OF MATERIALS" at 1153.5,-318.5 h60
  text "ASSEMBLY VARIANT:" at 1153,-434 h60
  text ".VariantName" at 2189,-434 h60
  text "PCB VIEWED FROM TOP SIDE" at -228.5,-655.67 h60
  text "BOARD #:" at 2248,-655.67 h60
  text ".PRJ_Number" at 2793.5,-655.67 h60
  text "REV:" at 3638,-655.67 h60
  text ".PCB_Rev" at 3929.5,-655.67 h60
  text "SVN REV:" at 4476,-655.67 h60
  text ".VersionControl_RevNumber" at 4982,-655.67 h60
  text "IGNORE ->" at -228.5,-858.49 h60
  text "PLOT NAME =" at -228.5,-1064.34 h60
  text ".plot_File_Name" at 577,-1064.34 h60
  text "GENERATED    :" at 2250,-1064.34 h60
  text ".Print_Date" at 3119.5,-1064.34 h60
  text ".Print_Time" at 3848.5,-1064.34 h60
  text "TEXAS INSTRUMENTS" at 5113,-1064.34 h60
M6 Assembly Bottom:
  lines w10: -292.5,-727.33 6309.5,-727.33 ; -290.5,-930.67 6309.5,-930.67 ; 1115.5,-1140.5 1115.5,-937.67 ; 1737.5,-727.33 1737.5,-524 ; 2577.5,-727.33 2577.5,-524 ; 3844.5,-1134 3844.5,-524 ; 4733.5,-1134 6309,-1134 6309,-524 -292.5,-524 -292.5,-1134 2304.5,-1134 6309.5,-1134 6309.5,-524
  text "COMPONENTS MARKED 'DNP' SHOULD NOT BE POPULATED, AND MAY NOT BE IN BILL OF MATERIALS" at 6102,-318 h60
  text ".VariantName" at 5058,-434 h60
  text "ASSEMBLY VARIANT:" at 6097,-434 h60
  text ".VersionControl_RevNumber" at 1035.5,-656.17 h60
  text "SVN REV:" at 1541.5,-656.17 h60
  text ".PCB_Rev" at 2088,-656.17 h60
  text "REV:" at 2379.5,-656.17 h60
  text ".PRJ_Number" at 3224,-656.17 h60
  text "BOARD #:" at 3769.5,-656.17 h60
  text "PCB VIEWED FROM BOTTOM SIDE" at 6246,-656.17 h60
  text "IGNORE ->" at 2547.85,-858.49 h60
  text "TEXAS INSTRUMENTS" at 904.5,-1064.84 h60
  text ".Print_Time" at 2169,-1064.84 h60
  text ".Print_Date" at 2898,-1064.84 h60
  text "GENERATED    :" at 3767.5,-1064.84 h60
  text ".plot_File_Name" at 5440.5,-1064.84 h60
  text "PLOT NAME =" at 6246,-1064.84 h60
M9 Title Sheet:
  drawing of 57 lines, arcs and shapes, not listed
  text "1" at 739.84,8036.5 h70
  text "2" at 3235.5,8036.5 h70
  text "3" at 5724.84,8036.5 h70
  text "4" at 8231.51,8036.5 h70
  text "5" at 10730.5,8036.5 h70
  text "6" at 13235.5,8036.5 h70
  text "A" at -416.5,6893.5 h70
  text "A" at 14383.5,6893.5 h70
  text "B" at -416.5,4513.5 h70
  text "B" at 14383.5,4513.5 h70
  text "C" at -416.5,2138.5 h70
  text "C" at 14383.5,2138.5 h70
  text "PROJECT TITLE:" at 11343.5,277.5 h45
  text ".PRJ_Title" at 11393.5,144.17 h70
  text "DESIGNED FOR:" at 11343.5,-23.5 h45
  text ".PRJ_Customer" at 11393.5,-163.5 h70
  text "D" at -416.5,-231.5 h70
  text "D" at 14383.5,-231.5 h70
  text "FILE NAME:" at 11343.5,-323.5 h45
  text ".PCB_File_Name_No_Path" at 11393.5,-443.5 h70
  text "Texas Instruments (TI) and/or its licensors do not warrant the accuracy or completeness of this specification" at 6374,-605.34 h45
  text "ENGINEER:" at 11343.5,-613.5 h45
  text "LAYOUT BY:" at 12848.5,-613.5 h45
  text "or any information contained therein. TI and/or its licensors do not warrant that this design will meet" at 6329.01,-718 h45
  text ".PRJ_Engineer" at 11393.5,-768.49 h70
  text ".PCB_Layout" at 12899,-768.49 h70
  text "the specifications, will be suitable for your application or fit for any particular purpose, or will operate in" at 6329.01,-830.67 h45
  text ".Layer_Name" at 577,-858.49 h60
  text "ALTIUM DESIGNER VERSION:" at 12848.5,-923.5 h45
  text "an implementation. TI and/or its licensors do not warrant that the design is production worthy. You should" at 6329.01,-943.33 h45
  text "completely validate and test your design implementation to confirm the system functionality for your application." at 6374,-1056 h45
  text ".print_Scale" at 11393.5,-1056.83 h70
  text ".Application_BuildNumber" at 12899,-1056.83 h70
  text "1" at 739.84,-1263.5 h70
  text "2" at 3235.5,-1263.5 h70
  text "3" at 5724.84,-1263.5 h70
  text "4" at 8231.51,-1263.5 h70
  text "5" at 10730.5,-1263.5 h70
  text "6" at 13235.5,-1263.5 h70
M10 Fab Notes:
  drawing of 203 lines, arcs and shapes, not listed
  text "DESIGN INFORMATION" at 12381.02,6810 h60
  text "(REFER ALSO ARRAY/PANEL PROFILING INFORMATION)" at 12019.46,6648.29 h60
  text "BOARD SIZE" at 11333.46,6644 h60
  text "1400MIL" at 11795.78,6516.18 h60
  text "X" at 12301.46,6516.18 h60
  text "4000MIL" at 12532.78,6516.18 h60
  text "Number of Layers :" at 11736.46,6319 h60
  text "4" at 12831.27,6309 h60
  text "MIN. TRACK WIDTH:" at 11736.46,6180 h60
  text "8" at 12832.7,6180 h60
  text "MIL" at 12987.46,6180 h60
  text "MIN. CLEARANCE:" at 11736.46,6048 h60
  text "7" at 12832.7,6048 h60
  text "MIL" at 12987.46,6048 h60
  text "MIN. VIA PAD SIZE:" at 11736.46,5916 h60
  text "22" at 12802.71,5916 h60
  text "MIL" at 12987.46,5916 h60
  text "0.05mm (2MIL)" at 12431.46,5774.29 h60
  text "MINIMUM ANNULAR RING" at 11407.23,5770 h60
  text "EXTERNAL" at 13139.46,5770 h60
  text "PER" at 11607.23,5652 h60
  text "IPC-D-275 CLASS 2 LEVEL C" at 11827.23,5652 h60
  text "MIL, HOLES" at 13315.46,5539.71 h60
  text "+/-" at 12923,5539 h60
  text "+/-" at 13777,5539 h60
  text "REGISTRATION TOLERANCES:" at 11407.23,5534 h60
  text "METAL" at 12607,5534 h60
  text "5" at 13183.2,5534 h60
  text "3" at 14016.2,5534 h60
  text "MIL" at 14132.46,5534 h60
  text "MATERIAL:" at 11332.46,5324.54 h60
  text "FR-4 High Tg" at 12318.9,5184.21 h60
  text "X" at 11610,5180 h60
  text "FR-4" at 11793.46,5175.64 h60
  text "OTHER" at 13241.46,5175.64 h60
  text "62 MIL (1.6mm) +/-10%" at 12073.56,5012.92 h60
  text "THICKNESS:" at 11407.23,5008.64 h60
  text "X" at 11945.4,5008.64 h60
  text "OTHER" at 13358.46,5008.64 h60
  text "TOLERANCE:" at 11407.23,4850.64 h60
  text "X" at 12246.53,4850.64 h60
  text "ANSI IPC-6012 TYPE 3 CLASS 2" at 12433.48,4850.64 h60
  text "OTHER +/-" at 12433.46,4694.64 h60
  text "BOW & TWIST:" at 11407.23,4537.64 h60
  text "X" at 12246.53,4537.64 h60
  text "ANSI IPC-6012 TYPE 3 CLASS 2" at 12433.48,4537.64 h60
  text "OTHER +/-" at 12433.46,4379.13 h60
  text "COPPER THICKNESS (FINISHED):" at 11332.46,4243.64 h60
  text "1.4MIL (1oz)" at 12212.46,4090.92 h60
  text "2MIL (1.4oz)" at 12979.46,4090.92 h60
  text "2.8MIL (2oz)" at 13706.46,4090.92 h60
  text "OUTER:" at 11689.46,4086.64 h60
  text "X" at 12084,4086 h60
  text "0.7MIL (0.5oz)" at 12562.46,3933.92 h60
  text "2.8MIL (2oz)" at 13406.46,3933.92 h60
  text "INNER SIGNAL:" at 11689.46,3929.64 h60
  text "X" at 12435.42,3929.64 h60
  text "DRILLING:" at 11332.46,3790.64 h60
  text "REFERENCE:" at 11407.23,3673.64 h60
  text "X" at 12055.46,3673.64 h60
  text "AS SHOWN" at 12242.46,3673.64 h60
  text "X" at 12956.46,3673.64 h60
  text "NC_DRILL FILES" at 13093.46,3673.64 h60
  text "PTH MIN COPPER THICKNESS:" at 11407.23,3515.64 h60
  text "X" at 12757.46,3515.64 h60
  text "1MIL" at 12894.46,3515.64 h60
  text "OTHER" at 13391.46,3515.64 h60
  text "BOARD FINISH:" at 11332.46,3356.64 h60
  text "SILKSCREEN:" at 11487.68,3238.64 h60
  text "X" at 12436.46,3238.64 h60
  text "TOP" at 12562.46,3238.64 h60
  text "X" at 12946.46,3238.64 h60
  text "BOTTOM" at 13073.46,3238.64 h60
  text "SILKSCREEN COLOR:" at 11487.68,3071.64 h60
  text "X" at 12435.42,3071.64 h60
  text "WHITE" at 12562.46,3071.64 h60
  text "OTHER" at 13073.46,3071.64 h60
  text "SOLDER RESIST COLOR:" at 11487.68,2901.64 h60
  text "X" at 12055.42,2742.44 h60
  text "GREEN" at 12182.46,2742.44 h60
  text "BLUE" at 12773.46,2742.44 h60
  text "OTHER" at 13311.46,2742.44 h60
  text "IMMERSION GOLD (ENIG)" at 12393.46,2553.92 h60
  text "SURFACE FINISH:" at 11332.46,2549.64 h60
  text "Pb-FREE HASL" at 13625.75,2549.64 h60
  text "HASL" at 12800.75,2404.64 h60
  text "OTHER" at 12393.46,2392.64 h60
  text "X" at 12200,2390 h60
  text "X" at 12205,2220 h60
  text "ARRAY/PANEL:" at 11332.46,2213.64 h60
  text "CUT AND TRIM PER MECH LAYER 1" at 12393.46,2209.35 h60
  text "N.C. ROUTE" at 12393.46,2057.64 h60
  text "V. SCORE" at 13259.46,2057.64 h60
  text "CERTIFICATION:" at 11332.46,1920.64 h60
  text "MATERIALS AND WORKMANSHIP FOR ALL PCBS" at 12057.46,1920.64 h60
  text "TO MEET OR EXCEED THE REQUIREMENTS OF:" at 12057.46,1822.64 h60
  text "X" at 11683.96,1686.13 h60
  text "ANSI IPC-A-600F CLASS ->" at 11822.96,1686.13 h60
  text "X" at 13462.02,1686.13 h60
  text "2" at 13580.96,1686.14 h60
  text "1" at 13265.96,1684.64 h60
  text "3" at 13934.96,1684.64 h60
  text "X" at 11686.02,1526.64 h60
  text "UL 94V-0" at 11822.96,1526.64 h60
  text "X" at 12498.02,1526.64 h60
  text "RoHS" at 12634.96,1526.64 h60
  text "OTHER" at 13279.36,1526.64 h60
  text "PER ORDER" at 13676.42,1526.64 h60
  text "ADDITIONAL REQUIREMENTS:" at 11332.46,1385.64 h60
  text "MICROSECTION:" at 11407.23,1270.64 h60
  text "YES" at 12312.96,1270.64 h60
  text "REQUIRED" at 13174.46,1114.49 h60
  text "BARE BOARD ELEC. TEST:" at 11407.23,1111.64 h60
  text "NONE" at 12712.96,1111.64 h60
  text "X" at 13047.46,1111.64 h60
  text "PER ORDER" at 13766.46,1111.64 h60
  text "MANUFACTURER'S ID/LOGO:" at 11407.23,954.64 h60
  text "RAIL" at 12872.96,950.35 h60
  text "METAL" at 13364.77,950.35 h60
  text "X" at 13735,950 h60
  text "SILK" at 13876.46,950.35 h60
  text ".Layer_Name" at 577,-858.49 h60
M11 Gerber Information:
  lines w10: -292,-930.17 6308,-930.17 ; -292,-726.83 6310,-726.83 ; -292,-523.5 -292,-1133.5 3713,-1133.5 6310,-1133.5 6310,-523.5 -291.5,-523.5 -291.5,-1133.5 1284,-1133.5 ; 2173,-1133.5 2173,-523.5 ; 3440,-726.83 3440,-523.5 ; 4280,-726.83 4280,-523.5 ; 4902,-1140 4902,-937.17
  text "ALL ARTWORK VIEWED FROM TOP SIDE" at -228.5,-655.67 h60
  text "BOARD #:" at 2248,-655.67 h60
  text ".PRJ_Number" at 2793.5,-655.67 h60
  text "REV:" at 3638,-655.67 h60
  text ".PCB_Rev" at 3929.5,-655.67 h60
  text "SVN REV:" at 4476,-655.67 h60
  text ".VersionControl_RevNumber" at 4982,-655.67 h60
  text "LAYER NAME =" at -228.5,-858.49 h60
  text "PLOT NAME =" at -228.5,-1064.34 h60
  text ".plot_File_Name" at 577,-1064.34 h60
  text "GENERATED    :" at 2250,-1064.34 h60
  text ".Print_Date" at 3119.5,-1064.34 h60
  text ".Print_Time" at 3848.5,-1064.34 h60
  text "TEXAS INSTRUMENTS" at 5113,-1064.34 h60
M12 Stackup:
  lines w12: 6485,6358.5 10140,6358.5 ; 6485,6575.5 10140,6575.5 ; 6425,4660 ccw(c6495,4660) 6495,4590 10130,4590 ccw(c10130,4660) 10200,4660 10200,6870 ccw(c10130,6870) 10130,6940 6495,6940 ccw(c6495,6870) 6425,6870 6425,4660
  text "Layer Stack Up Detail for: PMP7899 REVA.PcbDoc" at 6485,6701.35 h78
  text "Layer" at 6485,6494.5 h50
  text "Gerber" at 7796.95,6494.5 h50
  text "Copper" at 8430.85,6494.5 h50
  text "Dielectric" at 9146.39,6494.5 h50
  text "Name" at 6485,6394.5 h50
  text "Document" at 7796.95,6394.5 h50
  text "Thickness" at 8430.85,6394.5 h50
  text "Material" at 9146.39,6394.5 h50
  text "Top Solder Mask" at 6485,6222.29 h70
  text "(.GTS)" at 7796.95,6222.29 h70
  text "Solder Resist" at 9146.39,6222.29 h70
  text "Top Layer" at 6485,5961.88 h70
  text "(.GTL)" at 7796.95,5961.88 h70
  text "1.4mil" at 8430.85,5961.88 h70
  text "FR-4" at 9146.39,5831.67 h70
  text "MidLayer1" at 6485,5701.46 h70
  text "(.G1)" at 7796.95,5701.46 h70
  text "1.4mil" at 8430.85,5701.46 h70
  text "FR-4" at 9146.39,5571.25 h70
  text "MidLayer2" at 6485,5441.04 h70
  text "(.G2)" at 7796.95,5441.04 h70
  text "1.4mil" at 8430.85,5441.04 h70
  text "FR-4" at 9146.39,5310.83 h70
  text "Bottom Layer" at 6485,5180.63 h70
  text "(.GBL)" at 7796.95,5180.63 h70
  text "1.4mil" at 8430.85,5180.63 h70
  text "Bottom Solder Mask" at 6485,4920.21 h70
  text "(.GBS)" at 7796.95,4920.21 h70
  text "Solder Resist" at 9146.39,4920.21 h70
  text ".Layer_Name" at 577,-858.49 h60
M13 Component Bodies Top:
  text ".Layer_Name" at 577,-858.49 h60
M14 Component Bodies Bottom:
  text ".Layer_Name" at 577,-858.49 h60
M15 Courtyards Top:
  text ".Layer_Name" at 577,-858.49 h60
M16 Courtyards Bottom:
  text ".Layer_Name" at 577,-858.49 h60
Drill Drawing:
  text ".legend" at 4250,1475 h60
  text "Drill Table" at 4225,1275 h60
  text ".Layer_Name" at 577,-858.49 h60

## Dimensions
0,0 to 0,1400 on M2 Board Dimensions
0,0 to 4000,0 on M2 Board Dimensions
